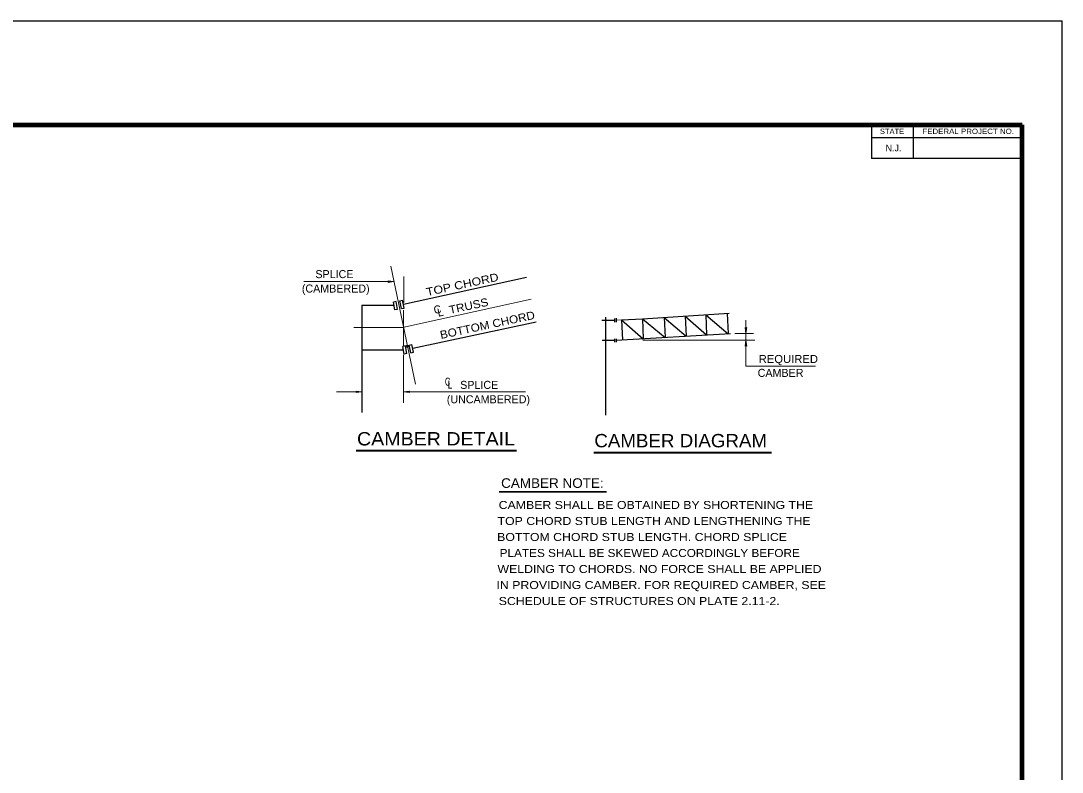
# Model space of a CAD drawing. Extents: x 312601.858 to 312602.699, y 144420.109 to 144420.704.
# Drawn here: x 312602.3083 to 312602.6988, y 144420.422 to 144420.7035 of the extents above; entities that cross this region are included whole.
import ezdxf
from ezdxf.enums import TextEntityAlignment as Align

# ---------------------------------------------------------------- set-up
doc = ezdxf.new("R2010")
doc.units = 0
doc.header["$LTSCALE"] = 0.0012
doc.header["$PDMODE"] = 32
doc.header["$PDSIZE"] = 0.0006
doc.linetypes.add('DOT_DASHED', pattern=[7.7, 5, -1.2, 0.3, -1.2])
for name, color, linetype, lineweight in [('1', 7, 'Continuous', 13), ('2', 7, 'Continuous', 13), ('39', 7, 'Continuous', 13), ('61', 7, 'Continuous', 25)]:
    doc.layers.add(name, color=color, linetype=linetype, lineweight=lineweight)

msp = doc.modelspace()

# ---------------------------------------------------------------- linework, layer by layer
at = {"layer": '1', "linetype": 'DOT_DASHED'}
for p, q in [((312602.4563, 144420.5674), (312602.447, 144420.6116)), ((312602.4519, 144420.6077), (312602.4519, 144420.598)), ((312602.4514, 144420.5886), (312602.4997, 144420.5992)), ((312602.4518, 144420.5951), (312602.4518, 144420.5819)), ((312602.4332, 144420.5886), (312602.4519, 144420.5886)), ((312602.4518, 144420.5784), (312602.4518, 144420.5604))]:
    msp.add_line(p, q, dxfattribs=at)
at = {"layer": '1'}
for p, q in [((312602.4144, 144420.6058), (312602.4482, 144420.6058)), ((312602.5315, 144420.5914), (312602.5335, 144420.5915)), ((312602.576, 144420.5863), (312602.5831, 144420.5863)), ((312602.5415, 144420.5838), (312602.5835, 144420.5838)), ((312602.5802, 144420.5838), (312602.5802, 144420.5741)), ((312602.5802, 144420.5741), (312602.6063, 144420.5741)), ((312602.4267, 144420.5645), (312602.4362, 144420.5645)), ((312602.4518, 144420.5645), (312602.4975, 144420.5645))]:
    msp.add_line(p, q, dxfattribs=at)
at = {"layer": '1', "lineweight": 25}
for p, q in [((312602.4518, 144420.5974), (312602.4979, 144420.6075)), ((312602.4362, 144420.597), (312602.4362, 144420.5567)), ((312602.4362, 144420.597), (312602.4482, 144420.597)), ((312602.449, 144420.5983), (312602.448, 144420.5981)), ((312602.4486, 144420.5952), (312602.448, 144420.5981)), ((312602.4496, 144420.5954), (312602.449, 144420.5983)), ((312602.4504, 144420.5986), (312602.4514, 144420.5988)), ((312602.4511, 144420.5957), (312602.4504, 144420.5986)), ((312602.4521, 144420.5959), (312602.4514, 144420.5988)), ((312602.4496, 144420.5954), (312602.4486, 144420.5952)), ((312602.4511, 144420.5957), (312602.4521, 144420.5959)), ((312602.5275, 144420.5925), (312602.5275, 144420.5557)), ((312602.5414, 144420.5918), (312602.5739, 144420.594)), ((312602.5574, 144420.5929), (312602.5578, 144420.5853)), ((312602.5574, 144420.5929), (312602.5654, 144420.5858)), ((312602.5652, 144420.5934), (312602.5654, 144420.5858)), ((312602.5652, 144420.5934), (312602.5736, 144420.5862)), ((312602.5732, 144420.5939), (312602.5736, 144420.5863)), ((312602.4553, 144420.5808), (312602.5016, 144420.5907)), ((312602.5262, 144420.5914), (312602.5309, 144420.5914)), ((312602.5309, 144420.592), (312602.5309, 144420.5906)), ((312602.5315, 144420.5921), (312602.5315, 144420.5907)), ((312602.5315, 144420.592), (312602.5315, 144420.5906)), ((312602.5335, 144420.5915), (312602.5414, 144420.5918)), ((312602.5335, 144420.5915), (312602.5339, 144420.5839)), ((312602.5335, 144420.5915), (312602.5417, 144420.5844)), ((312602.5414, 144420.5918), (312602.5417, 144420.5844)), ((312602.5414, 144420.5918), (312602.5499, 144420.5849)), ((312602.5495, 144420.5923), (312602.5499, 144420.5849)), ((312602.5495, 144420.5923), (312602.5578, 144420.5853)), ((312602.5315, 144420.5838), (312602.5744, 144420.5863)), ((312602.4525, 144420.5817), (312602.4515, 144420.5815)), ((312602.4531, 144420.5788), (312602.4525, 144420.5817)), ((312602.4539, 144420.582), (312602.4549, 144420.5822)), ((312602.4546, 144420.5791), (312602.4539, 144420.582)), ((312602.5263, 144420.5838), (312602.5309, 144420.5838)), ((312602.5309, 144420.5844), (312602.5309, 144420.5831)), ((312602.5315, 144420.5844), (312602.5315, 144420.5831)), ((312602.4362, 144420.5802), (312602.4518, 144420.5802))]:
    msp.add_line(p, q, dxfattribs=at)
at = {"layer": '1', "lineweight": 40}
for p, q in [((312602.434, 144420.5425), (312602.4942, 144420.5425)), ((312602.5232, 144420.5417), (312602.5898, 144420.5417))]:
    msp.add_line(p, q, dxfattribs=at)
at = {"layer": '1'}
for points in [[(312602.446, 144420.6061), (312602.4482, 144420.6058), (312602.446, 144420.6055), (312602.4462, 144420.6058)], [(312602.5805, 144420.5886), (312602.5802, 144420.5863), (312602.5799, 144420.5886), (312602.5802, 144420.5883)], [(312602.5799, 144420.5816), (312602.5802, 144420.5838), (312602.5805, 144420.5816), (312602.5802, 144420.5818)], [(312602.434, 144420.5648), (312602.4362, 144420.5645), (312602.434, 144420.5642), (312602.4342, 144420.5645)], [(312602.4541, 144420.5642), (312602.4518, 144420.5645), (312602.4541, 144420.5648), (312602.4538, 144420.5645)]]:
    msp.add_lwpolyline(points, close=True, dxfattribs=at)
msp.add_lwpolyline([(312602.5802, 144420.5913), (312602.5802, 144420.5863), (312602.5802, 144420.5838)], dxfattribs=at)
at = {"layer": '1', "lineweight": 25}
for points in [[(312602.4531, 144420.5788), (312602.4521, 144420.5786), (312602.4515, 144420.5815)], [(312602.4546, 144420.5791), (312602.4556, 144420.5793), (312602.4549, 144420.5822)]]:
    msp.add_lwpolyline(points, dxfattribs=at)
at = {"layer": '1'}
for p in [(312602.4532, 144420.5816), (312602.4533, 144420.5816), (312602.4533, 144420.5815)]:
    msp.add_point(p, dxfattribs=at)
at = {"layer": '2', "lineweight": 35}
msp.add_line((312602.4877, 144420.527), (312602.5279, 144420.527), dxfattribs=at)
at = {"layer": '39', "lineweight": 25}
for p, q in [((312601.8578, 144420.7035), (312602.6988, 144420.7035)), ((312602.6988, 144420.1095), (312602.6988, 144420.7035)), ((312602.5735, 144420.6645), (312602.6838, 144420.6645)), ((312602.6838, 144420.6514), (312602.6838, 144420.6645))]:
    msp.add_line(p, q, dxfattribs=at)
at = {"layer": '39', "lineweight": 158}
msp.add_line((312602.6838, 144420.1247), (312602.6838, 144420.6645), dxfattribs=at)
msp.add_lwpolyline([(312601.9088, 144420.1247), (312601.9088, 144420.6645), (312602.6838, 144420.6645)], dxfattribs=at)
at = {"layer": '61'}
for p, q in [((312602.6273, 144420.6645), (312602.6273, 144420.6519)), ((312602.6429, 144420.6645), (312602.6429, 144420.6519)), ((312602.6838, 144420.6597), (312602.6273, 144420.6597)), ((312602.6838, 144420.6519), (312602.6273, 144420.6519))]:
    msp.add_line(p, q, dxfattribs=at)

# ---------------------------------------------------------------- texts
at = {"layer": '2'}
for s, p in [('SPLICE', (312602.4259, 144420.6071)), ('(CAMBERED)', (312602.4264, 144420.6017)), ('CAMBER', (312602.5932, 144420.5701)), ('SPLICE', (312602.4802, 144420.5656)), ('(UNCAMBERED)', (312602.48365, 144420.5602))]:
    msp.add_text(s, height=0.003, dxfattribs=at).set_placement(p, align=Align.CENTER)
for s, height, width, p in [('TOP CHORD', 0.002999, 1.15, (312602.47418, 144420.60325)), ('C', 0.003, 0.95, (312602.46483, 144420.59389)), ('TRUSS', 0.002999, 1.1, (312602.47654, 144420.59523)), ('BOTTOM CHORD', 0.002999, 1.1, (312602.48358, 144420.58808))]:
    msp.add_text(s, height=height, rotation=12.116, dxfattribs=dict(at, width=width)).set_placement(p, align=Align.CENTER)
msp.add_text('L', height=0.003, rotation=12.116, dxfattribs=at).set_placement((312602.46593, 144420.59284), align=Align.CENTER)
for s, height, width, p in [('REQUIRED ', 0.003, 1.05, (312602.5967, 144420.5753)), ('C', 0.003, 0.7, (312602.46835, 144420.5668)), ('L', 0.003, 0.75, (312602.46925, 144420.5657)), ('CAMBER DETAIL', 0.005, 1.1, (312602.464, 144420.5444)), ('CAMBER DIAGRAM', 0.005, 1.05, (312602.55575, 144420.5437)), ('CAMBER NOTE:', 0.0036, 1.05, (312602.50765, 144420.5285)), ('CAMBER SHALL BE OBTAINED BY SHORTENING THE ', 0.003, 1.15, (312602.5471, 144420.5206)), ('TOP CHORD STUB LENGTH AND LENGTHENING THE  ', 0.003, 1.15, (312602.54705, 144420.5146)), ('BOTTOM CHORD STUB LENGTH. CHORD SPLICE ', 0.003, 1.15, (312602.5419, 144420.5086)), ('PLATES SHALL BE SKEWED ACCORDINGLY BEFORE', 0.003, 1.1, (312602.54415, 144420.5026)), ('WELDING TO CHORDS. NO FORCE SHALL BE APPLIED', 0.003, 1.15, (312602.5478, 144420.4966)), ('IN PROVIDING CAMBER. FOR REQUIRED CAMBER, SEE', 0.003, 1.15, (312602.54845, 144420.4906)), ('SCHEDULE OF STRUCTURES ON PLATE 2.11-2.', 0.003, 1.15, (312602.5402, 144420.4846))]:
    msp.add_text(s, height=height, dxfattribs=dict(at, width=width)).set_placement(p, align=Align.CENTER)
at = {"layer": '61'}
for s, width, p in [('STATE', 1.05, (312602.635, 144420.6611)), ('FEDERAL PROJECT NO.', 1.1, (312602.66355, 144420.6611))]:
    msp.add_text(s, height=0.00201, dxfattribs=dict(at, width=width)).set_placement(p, align=Align.CENTER)
msp.add_text('N.J.', height=0.002512, dxfattribs=at).set_placement((312602.63555, 144420.6546), align=Align.CENTER)

doc.saveas('drawing.dxf')
